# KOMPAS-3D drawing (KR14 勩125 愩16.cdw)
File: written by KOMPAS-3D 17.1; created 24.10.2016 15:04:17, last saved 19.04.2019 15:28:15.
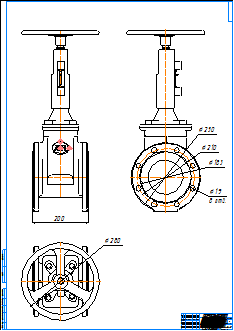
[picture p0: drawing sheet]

Sheet 1: A0, portrait

Title block, sheet 1: name: KR14 Ду125 Ру16; material: Внимание! Данный продукт является объектом авторского права ООО «Торговый Дом АДЛ». / Запрещается изменение, копирование, распространение / (в том числе путем копирования на другие сайты и ресурсы в Интернете) / или любое иное использование информации и объектов без предварительного / согласия правообладателя (ООО «Торговый Дом АДЛ»).; mass: 51,5; sheets: 1; organisation: ООО "Торговый дом АДЛ"; sheet format: A0; stored path: \\adlc.lan\data\АДЛ_ПКД\3D-модели\ADL production\Клиновые задвижки серии KR ГРАНАР\Клиновые задвижки KR14\kompas 2d\KR14 Ду125 Ру16.cdw

Views: Вид 1
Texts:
  Klimkovich
  ADL
Dimensions and other numbers on the sheet: 200; 1:1; 1; 51,5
